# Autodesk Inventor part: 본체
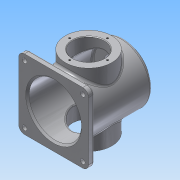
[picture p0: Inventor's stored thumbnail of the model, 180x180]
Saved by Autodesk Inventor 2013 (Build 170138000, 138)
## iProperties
Created: 2015-10
Part Number: 본체
Material: 알루미늄 6061
Document SubType Name: Modeling
Designer: Administrator
Density: 2.71 g/cm^3
Mass: 956.334 g
Surface Area: 1020.53 cm^2
Volume: 352.891 cm^3
Author: Administrator
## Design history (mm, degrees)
sketch "스케치1"
  geometry: C1 r 50 at (0, 0); 1 further point
  constraints: 1 centre point, 1 coincident
  dimensions: "d0" = 50 radius of C1
extrude "돌출1" new body sketch "스케치1" stored distance "d1" = 110; taper "d2" = 0 deg
sketch "스케치2"
  geometry: L1 (60, -60)-(-60, -60); L2 (-60, -60)-(-60, 60); L3 (-60, 60)-(60, 60); L4 (60, 60)-(60, -60); L5 (60, -60)-(-60, 60); L6 (-60, -60)-(60, 60); C1 r 50 at (0, 0) reference
  constraints: 12 end point, 2 midpoint, 2 parallel, 1 horizontal, 1 perpendicular
  dimensions: "d5" = 120 distance of L2.end L3.end; "d6" = 120 distance of L1.end L2.end
extrude "돌출2" join sketch "스케치2" distance "d7" = 10; taper "d8" = 0 deg
node "작업 평면1"
sketch "스케치3"
  geometry: C1 r 40 at (0, 0); 1 further point
  constraints: 1 centre point, 1 coincident
  dimensions: "d10" = 80 diameter of C1
extrude "돌출3" join sketch "스케치3" stored distance "d11" = 10; taper "d12" = 0 deg
node "작업 평면2"
sketch "스케치4"
  geometry: L1 (60, -65)-(-60, -65) reference; C1 r 40 at (0, -5); 1 further point
  constraints: 1 centre point, 1 vertical alignment
  dimensions: "d14" = 80 diameter of C1; "d15" = 60 distance from line of L1 C1.centre
extrude "돌출4" join sketch "스케치4" stored distance "d16" = 10; taper "d17" = 0 deg
sketch "스케치5"
  geometry: C1 r 40 at (0, 0) reference; C2 r 27 at (0, 0)
  constraints: 1 centre point, 1 coincident
  dimensions: "d18" = 54 diameter of C2
extrude "돌출5" cut sketch "스케치5" distance "d19" = 13; taper "d20" = 0 deg
sketch "스케치6"
  geometry: C1 r 27 at (0, 0) reference; C2 r 45 at (0, 0)
  constraints: 1 centre point, 1 coincident
  dimensions: "d21" = 90 diameter of C2
extrude "돌출6" cut sketch "스케치6" distance "d22" = 112; taper "d23" = 0 deg
hole "구멍1" diameter "d26" = 54; stored, may be unused: countersink angle "d30" = 90 deg, drill point angle "d32" = 118 deg; dims "d24" = 10, "d25" = 10, "d27" = 6, "d28" = 4, "d29" = 2, "d31" = 8
node "작업 평면3"
sketch "스케치8"
  geometry: L1 (65, 60)-(65, -60) reference; 2 further points
  constraints: 1 horizontal alignment, 1 other
  dimensions: "d45" = 70 distance from line of L1 point (-5, 0)
feature "엠보싱1" sketch "스케치8" dims "d46" = 0.5, "d47" = 0
sketch "스케치9"
  geometry: L1 (0, 0)-(0, 40); L2 (0, 0)-(22.981, 22.981); 1 further point
  constraints: 4 end point, 1 coincident, 1 vertical, 1 vertical alignment, 1 other
  dimensions: "d48" = 45 deg angle of L2 L1; "d49" = 32.5 distance of L1.start L2.end
hole "구멍3" sketch "스케치9" at (22.981, 22.981) diameter "d50" = 3.242; stored, may be unused: countersink angle "d54" = 90 deg, drill point angle "d56" = 118 deg; dims "d51" = 8, "d52" = 4, "d53" = 2, "d55" = 10
fillet "모깎기1" dims "d60" = 10
sketch "스케치10"
  geometry: C1 r 50 at (0, 0) reference; 4 further points
  dimensions: "d61" = 100 distance of point (50, 50) point (-50, 50); "d63" = 100 distance of point (-50, -50) point (-50, 50); "d64" = 100 distance of point (50, -50) point (-50, -50); "d65" = 100 distance of point (50, -50) point (50, 50); "d66" = 50 horizontal distance of C1.centre point (-50, 50); "d67" = 50 horizontal distance of C1.centre point (-50, 50); "d68" = 50 horizontal distance of C1.centre point (-50, -50); "d69" = 50 horizontal distance of C1.centre point (50, -50)
hole "구멍4" sketch "스케치10" at (-50, 50), (50, 50), (50, -50), (-50, -50) diameter "d70" = 8; stored, may be unused: countersink angle "d74" = 90 deg, drill point angle "d76" = 0 deg; dims "d71" = 8, "d72" = 4, "d73" = 2, "d75" = 10
fillet "모깎기2" dims "d77" = 5
fillet "모깎기3" dims "d78" = 3
fillet "모깎기4" dims "d79" = 5
fillet "모깎기5" dims "d80" = 3
fillet "모깎기6" dims "d81" = 3
fillet "모깎기7" dims "d82" = 3
chamfer "모따기2" distance "d86" = 3; stored, may be unused: second distance "d87" = 2, angle "d88" = 45 deg
sketch "스케치11"
  geometry: C1 r 27 at (0, 0) reference; C2 r 40 at (0, 0) reference; 1 further point
extrude "돌출7" join sketch "스케치11" distance "d89" = 2; taper "d90" = 0 deg
sketch "스케치12"
  geometry: C1 r 27 at (0, 0) reference; C2 r 40 at (0, 0) reference; 1 further point
extrude "돌출8" join sketch "스케치12" distance "d91" = 2; taper "d92" = 0 deg
sketch "스케치13"
  geometry: L1 (0, 0)-(0, 32.5); C1 r 40 at (0, 0) reference; 2 further points
  constraints: 2 end point, 1 coincident, 1 vertical
  dimensions: "d93" = 32.5 distance of L1.start L1.end
hole "구멍5" sketch "스케치13" at (0, 32.5) diameter "d94" = 3.242; stored, may be unused: countersink angle "d98" = 90 deg, drill point angle "d100" = 118 deg; dims "d95" = 8, "d96" = 4, "d97" = 2, "d99" = 10
chamfer "모따기3" distance "d104" = 1; stored, may be unused: second distance "d105" = 2, angle "d106" = 45 deg
node "솔리드1"
mirror "대칭1"
pattern_circular "원형 패턴2" dims angle "d58" = 360 deg
pattern_circular "원형 패턴3" dims angle "d102" = 360 deg
mirror "대칭2"
other parameters: "d9" = -125, "d44" = -74
